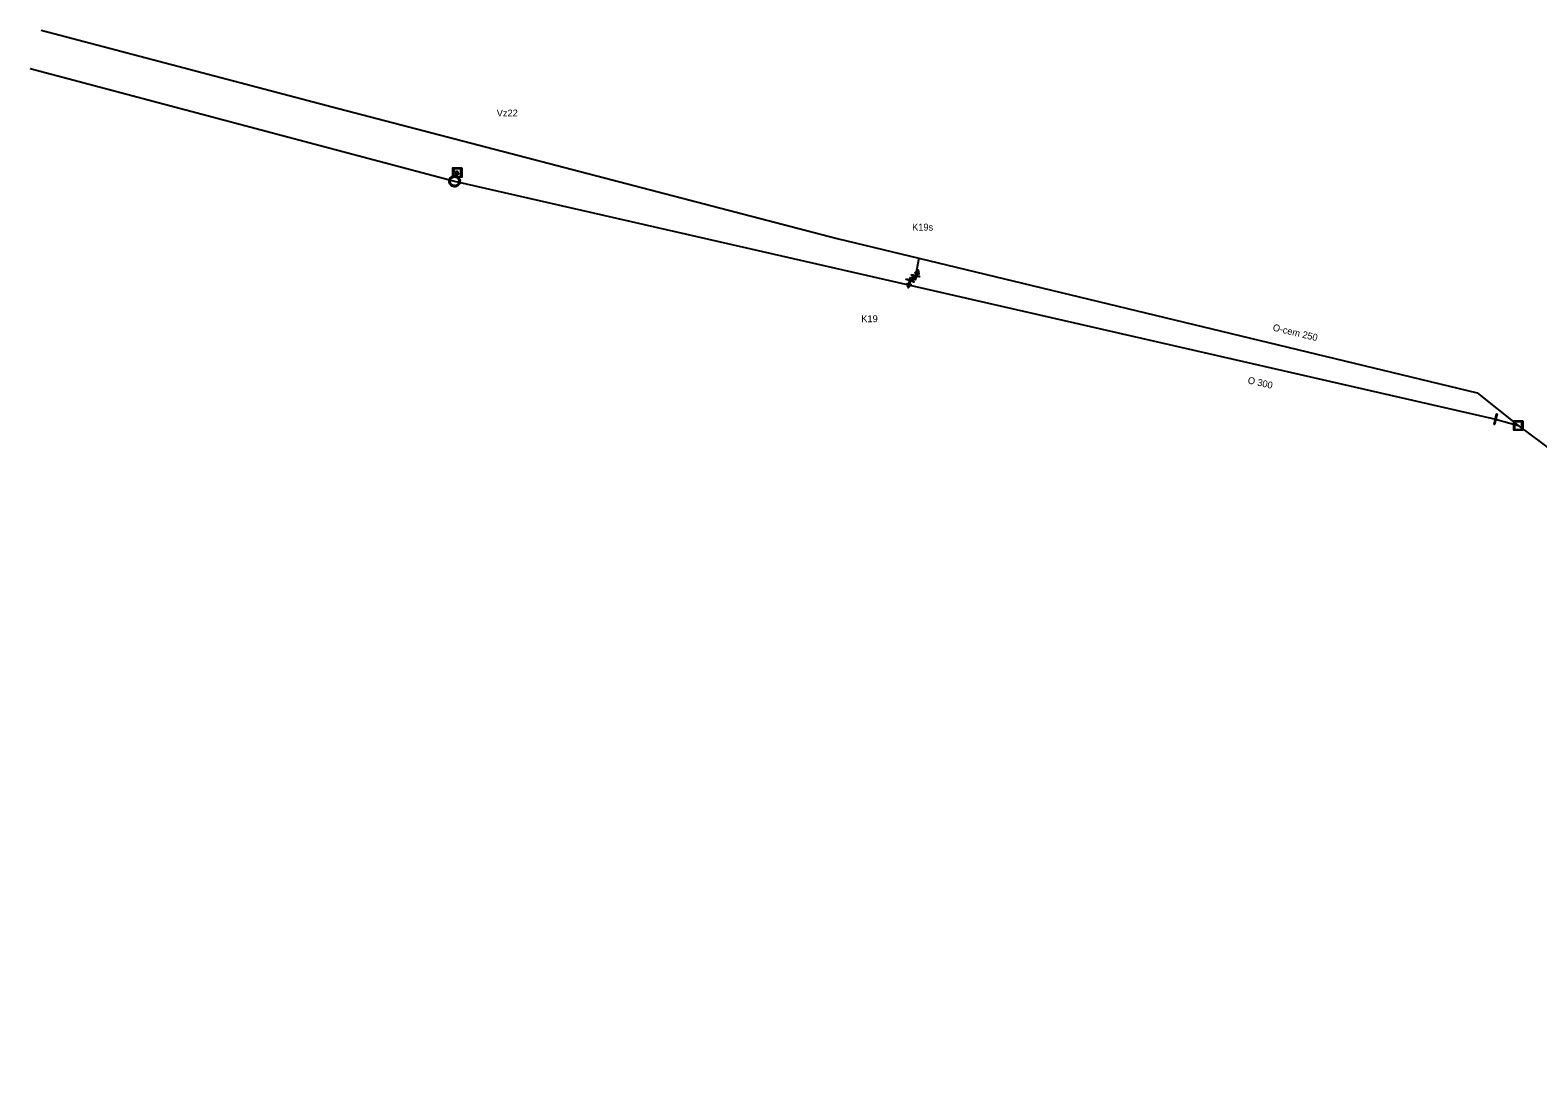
# Model space of a CAD drawing. Extents: x -638315 to -636370, y -1116147 to -1115110.
# Drawn here: x -638315.4 to -638032, y -1115305.5 to -1115110 of the extents above; entities that cross this region are included whole.
import ezdxf

# ---------------------------------------------------------------- set-up
doc = ezdxf.new("R2010")
doc.units = 0
for name, color, linetype in [('Default', 7, 'Continuous'), ('VP Hydrant', 7, 'Continuous'), ('VP Hydrant - popis', 7, 'Continuous'), ('VP Označení šachty', 7, 'Continuous'), ('VP Řad', 7, 'Continuous'), ('VP Řad - popis', 7, 'Continuous'), ('VP Šachta', 7, 'Continuous'), ('VP Šoupě', 7, 'Continuous')]:
    doc.layers.add(name, color=color, linetype=linetype)

msp = doc.modelspace()

# ---------------------------------------------------------------- linework, layer by layer
at = {"layer": 'Default'}
for points in [[(-638235.28, -1115137.42), (-638234.94, -1115137.54), (-638234.75, -1115137.86), (-638234.55, -1115138.22), (-638234.65, -1115138.62), (-638234.76, -1115139.02), (-638235.12, -1115139.23), (-638235.48, -1115139.43), (-638235.88, -1115139.33), (-638236.28, -1115139.22), (-638236.48, -1115138.86), (-638236.69, -1115138.5), (-638236.59, -1115138.1), (-638236.48, -1115137.7), (-638236.12, -1115137.49), (-638235.81, -1115137.31), (-638235.45, -1115137.37)], [(-638235.41, -1115137.57), (-638235.74, -1115137.49), (-638236.03, -1115137.65), (-638236.32, -1115137.82), (-638236.41, -1115138.15), (-638236.49, -1115138.48), (-638236.32, -1115138.77), (-638236.16, -1115139.06), (-638235.83, -1115139.14), (-638235.5, -1115139.23), (-638235.21, -1115139.06), (-638234.92, -1115138.89), (-638234.84, -1115138.57), (-638234.75, -1115138.24), (-638234.92, -1115137.95), (-638235.09, -1115137.66), (-638235.41, -1115137.57)], [(-638235.7, -1115136.41), (-638235.71, -1115136.35), (-638235.71, -1115136.32), (-638235.73, -1115136.35), (-638235.75, -1115136.39)]]:
    msp.add_open_spline(points, degree=3, dxfattribs=at)
at = {"layer": 'VP Hydrant'}
for points in [[(-638236, -1115136.64), (-638235.73, -1115136.27), (-638235.67, -1115136.28), (-638235.61, -1115136.74), (-638235.67, -1115136.73), (-638235.69, -1115136.59), (-638235.86, -1115136.54), (-638235.94, -1115136.65), (-638236, -1115136.64)], [(-638235.75, -1115136.39), (-638235.83, -1115136.5)], [(-638235.83, -1115136.5), (-638235.69, -1115136.54), (-638235.7, -1115136.41)], [(-638235.45, -1115137.37), (-638235.32, -1115136.88), (-638235.57, -1115136.82), (-638235.11, -1115136.43), (-638234.9, -1115137), (-638235.15, -1115136.93)], [(-638235.15, -1115136.93), (-638235.28, -1115137.42)], [(-638149.64, -1115156.65), (-638149.89, -1115156.6), (-638150.12, -1115157.69), (-638149.82, -1115157.76), (-638150.34, -1115158.41), (-638150.55, -1115157.6), (-638150.24, -1115157.67), (-638149.98, -1115156.45), (-638149.61, -1115156.53), (-638149.54, -1115156.16), (-638149.41, -1115156.19), (-638149.49, -1115156.55), (-638149.13, -1115156.63), (-638149.16, -1115156.75), (-638149.52, -1115156.68), (-638149.6, -1115157.04), (-638149.72, -1115157.01), (-638149.64, -1115156.65)], [(-638149.39, -1115156.65), (-638149.15, -1115156.73), (-638148.8, -1115155.66), (-638149.1, -1115155.57), (-638148.51, -1115154.97), (-638148.38, -1115155.8), (-638148.69, -1115155.7), (-638149.07, -1115156.89), (-638149.43, -1115156.77), (-638149.54, -1115157.13), (-638149.66, -1115157.09), (-638149.54, -1115156.73), (-638149.9, -1115156.62), (-638149.86, -1115156.5), (-638149.51, -1115156.61), (-638149.39, -1115156.26), (-638149.27, -1115156.3), (-638149.39, -1115156.65)]]:
    msp.add_lwpolyline(points, dxfattribs=at)
at = {"layer": 'VP Řad'}
for points in [[(-638313.31, -1115109.95), (-638257.43, -1115124.68), (-638163.69, -1115149.12), (-638148.35, -1115152.82), (-638043.45, -1115178.1), (-638035.71, -1115184.26)], [(-638315.39, -1115117.17), (-638235.62, -1115138.36), (-638150.3, -1115157.81), (-638150.04, -1115157.87), (-638039.97, -1115183.07), (-638035.71, -1115184.26)], [(-638148.35, -1115152.82), (-638149.01, -1115156.1), (-638149.14, -1115156.66)], [(-638150.3, -1115157.81), (-638150.02, -1115157.01), (-638149.89, -1115156.59)], [(-638035.71, -1115184.26), (-637945.92, -1115250.97), (-637839.61, -1115300.79), (-637684.14, -1115342.16), (-637665.64, -1115375.46)]]:
    msp.add_lwpolyline(points, dxfattribs=at)
at = {"layer": 'VP Šachta'}
for points in [[(-638234.28, -1115135.84), (-638234.28, -1115137.58), (-638235.98, -1115137.58), (-638235.98, -1115135.84), (-638234.28, -1115135.84)], [(-638235.84, -1115135.99), (-638235.84, -1115137.43), (-638234.43, -1115137.43), (-638234.43, -1115135.99), (-638235.84, -1115135.99)], [(-638034.87, -1115183.4), (-638034.87, -1115185.14), (-638036.56, -1115185.14), (-638036.56, -1115183.4), (-638034.87, -1115183.4)], [(-638036.42, -1115183.54), (-638036.42, -1115184.99), (-638035.01, -1115184.99), (-638035.01, -1115183.54), (-638036.42, -1115183.54)]]:
    msp.add_lwpolyline(points, dxfattribs=at)
at = {"layer": 'VP Šoupě'}
for points in [[(-638150.71, -1115156.71), (-638149.3, -1115157.21), (-638149.33, -1115157.3), (-638150.75, -1115156.8), (-638150.71, -1115156.71)], [(-638149.74, -1115155.9), (-638148.27, -1115156.2), (-638148.29, -1115156.29), (-638149.76, -1115155.99), (-638149.74, -1115155.9)], [(-638040.26, -1115184.03), (-638039.81, -1115182.08), (-638039.69, -1115182.11), (-638040.14, -1115184.06), (-638040.26, -1115184.03)]]:
    msp.add_lwpolyline(points, dxfattribs=at)

# ---------------------------------------------------------------- texts
at = {"layer": 'VP Hydrant - popis'}
for s, p in [('K19s', (-638149.63, -1115147.63)), ('K19', (-638159.18, -1115164.84))]:
    msp.add_text(s, height=1.3, dxfattribs=at).set_placement(p)
at = {"layer": 'VP Označení šachty'}
msp.add_text('Vz22', height=1.3, dxfattribs=at).set_placement((-638227.7, -1115126.18))
at = {"layer": 'VP Řad - popis'}
for s, rotation, p in [('O-cem 250', 346.4491, (-638081.94, -1115166.4)), ('O 300', 347, (-638086.64, -1115176.32))]:
    msp.add_text(s, height=1.3, rotation=rotation, dxfattribs=at).set_placement(p)

doc.saveas('drawing.dxf')
